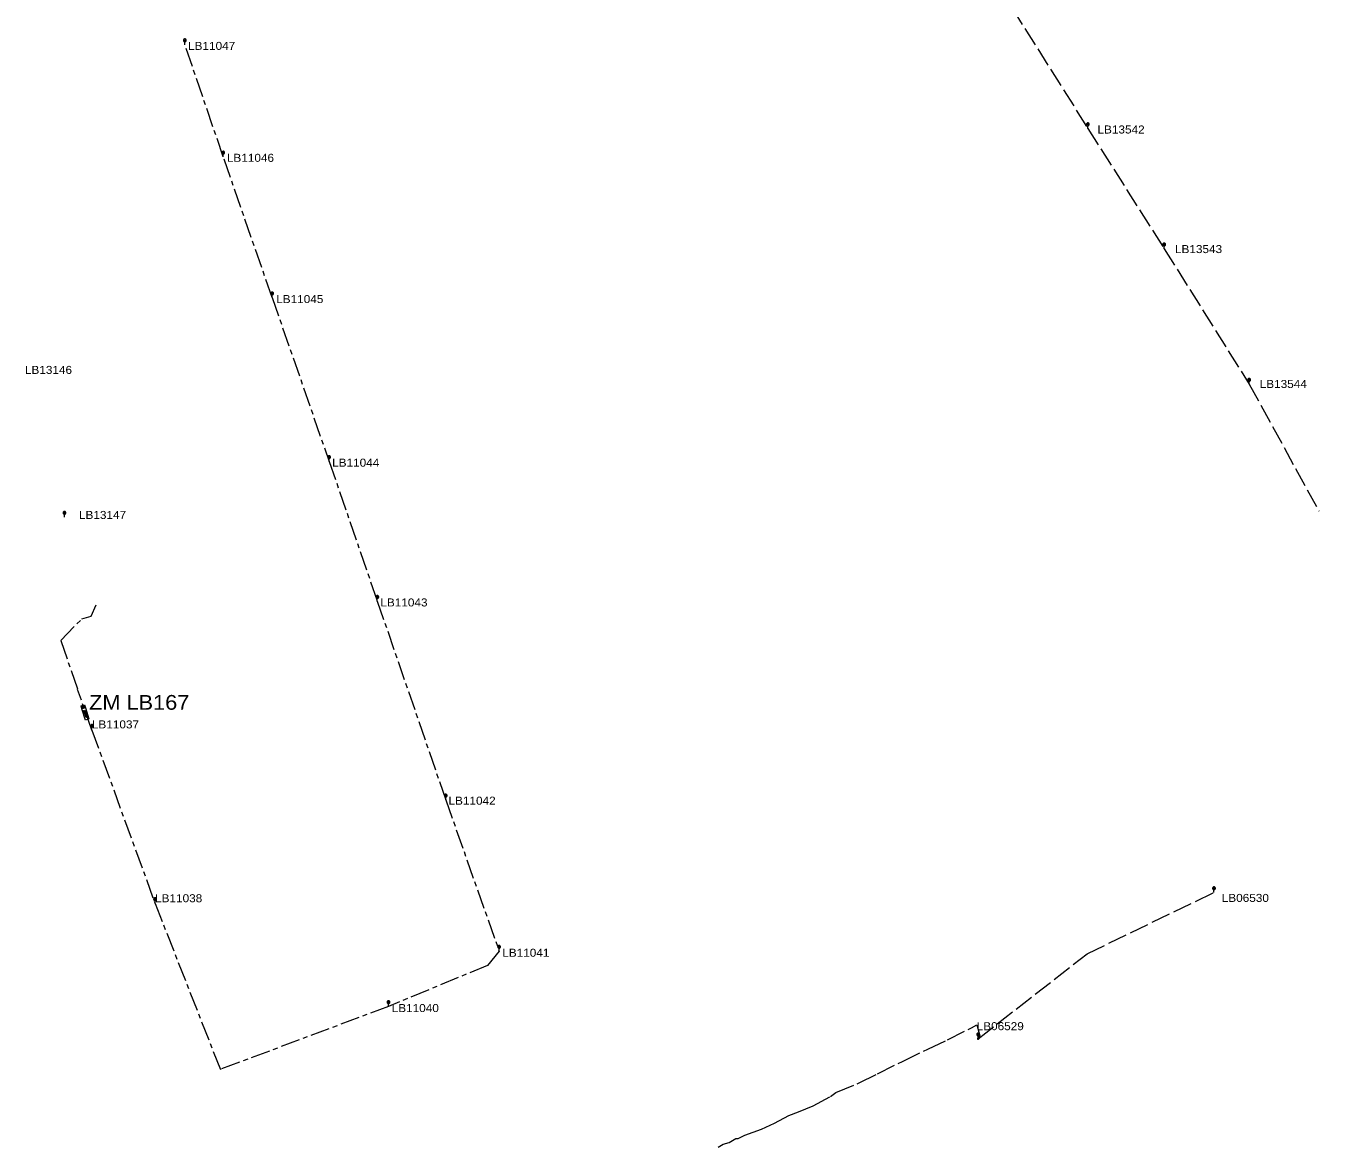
# Model space of a CAD drawing. Extents: x -691843 to -691118, y -976392 to -975793.
# Drawn here: x -691478 to -691127.9, y -976386.7 to -976083.1 of the extents above; entities that cross this region are included whole.
import ezdxf

# ---------------------------------------------------------------- set-up
doc = ezdxf.new("R2010")
doc.units = 0
doc.header["$LTSCALE"] = 0.87
doc.linetypes.add('LONG_DASH_SHORT_DASH', pattern=[9.9, 6, -1.2, 1.5, -1.2])
doc.linetypes.add('LONG_DASHED', pattern=[7.5, 6, -1.5])
doc.layers.add('1', color=7, linetype='Continuous', lineweight=13)

msp = doc.modelspace()

# ---------------------------------------------------------------- hatches: boundary and pattern name
at = {"layer": '1'}
for points in [[(-691462.091, -976266.926), (-691461.855, -976267.69), (-691462.81, -976267.986), (-691463.046, -976267.222)], [(-691462.742, -976267.36), (-691462.264, -976267.212), (-691462.15, -976267.58), (-691462.229, -976267.605), (-691462.31, -976267.345), (-691462.415, -976267.378), (-691462.345, -976267.603), (-691462.424, -976267.628), (-691462.494, -976267.402), (-691462.621, -976267.442), (-691462.541, -976267.701), (-691462.628, -976267.728)], [(-691462.059, -976268.381), (-691461.467, -976270.292), (-691461.658, -976270.351), (-691462.25, -976268.441)]]:
    msp.add_hatch(color=256, dxfattribs=at).paths.add_polyline_path(points)

# ---------------------------------------------------------------- linework, layer by layer
for p, q in [((-691435.212, -976086.724), (-691434.682, -976087.254)), ((-691435.212, -976087.254), (-691434.682, -976086.724)), ((-691434.947, -976088.139), (-691434.947, -976087.364)), ((-691190.775, -976109.465), (-691190.245, -976109.995)), ((-691190.775, -976109.995), (-691190.245, -976109.465)), ((-691190.51, -976110.88), (-691190.51, -976110.105)), ((-691424.811, -976117.136), (-691424.281, -976117.666)), ((-691424.811, -976117.666), (-691424.281, -976117.136)), ((-691424.546, -976118.551), (-691424.546, -976117.776)), ((-691170.125, -976142.015), (-691169.595, -976142.545)), ((-691170.125, -976142.545), (-691169.595, -976142.015)), ((-691169.86, -976143.43), (-691169.86, -976142.655)), ((-691411.569, -976155.247), (-691411.039, -976155.777)), ((-691411.569, -976155.777), (-691411.039, -976155.247)), ((-691411.304, -976156.662), (-691411.304, -976155.887)), ((-691147.115, -976178.655), (-691146.585, -976179.185)), ((-691147.115, -976179.185), (-691146.585, -976178.655)), ((-691146.85, -976180.07), (-691146.85, -976179.295)), ((-691396.157, -976199.577), (-691395.627, -976200.107)), ((-691396.157, -976200.107), (-691395.627, -976199.577)), ((-691395.892, -976200.992), (-691395.892, -976200.217)), ((-691467.801, -976214.654), (-691467.271, -976215.184)), ((-691467.801, -976215.184), (-691467.271, -976214.654)), ((-691467.536, -976216.069), (-691467.536, -976215.294)), ((-691383.111, -976237.436), (-691382.581, -976237.966)), ((-691383.111, -976237.966), (-691382.581, -976237.436)), ((-691382.846, -976238.851), (-691382.846, -976238.076)), ((-691460.372, -976272.356), (-691459.842, -976272.886)), ((-691460.372, -976272.886), (-691459.842, -976272.356)), ((-691460.107, -976273.771), (-691460.107, -976272.996)), ((-691364.591, -976291.215), (-691364.061, -976291.745)), ((-691364.591, -976291.745), (-691364.061, -976291.215)), ((-691364.326, -976292.63), (-691364.326, -976291.855)), ((-691156.645, -976316.315), (-691156.115, -976316.845)), ((-691156.645, -976316.845), (-691156.115, -976316.315)), ((-691443.282, -976319.263), (-691442.752, -976319.793)), ((-691443.282, -976319.793), (-691442.752, -976319.263)), ((-691443.017, -976320.678), (-691443.017, -976319.903)), ((-691156.38, -976317.73), (-691156.38, -976316.955)), ((-691350.155, -976332.168), (-691349.625, -976332.698)), ((-691350.155, -976332.698), (-691349.625, -976332.168)), ((-691349.89, -976333.583), (-691349.89, -976332.808)), ((-691380.08, -976347.145), (-691379.55, -976347.675)), ((-691380.08, -976347.675), (-691379.55, -976347.145)), ((-691379.815, -976348.56), (-691379.815, -976347.785)), ((-691220.475, -976355.885), (-691219.945, -976356.415)), ((-691220.475, -976356.415), (-691219.945, -976355.885)), ((-691220.21, -976357.3), (-691220.21, -976356.525))]:
    msp.add_line(p, q, dxfattribs=at)
at = {"layer": '1', "linetype": 'LONG_DASHED'}
for p, q in [((-691190.51, -976110.88), (-691169.86, -976143.43)), ((-691169.86, -976143.43), (-691146.85, -976180.07)), ((-691146.85, -976180.07), (-691127.92, -976214.52))]:
    msp.add_line(p, q, dxfattribs=at)
at = {"layer": '1', "linetype": 'LONG_DASH_SHORT_DASH'}
for p, q in [((-691411.304, -976156.662), (-691395.892, -976200.992)), ((-691462.797, -976243.605), (-691460.288, -976242.863)), ((-691460.288, -976242.863), (-691458.924, -976239.813)), ((-691468.513, -976249.481), (-691462.797, -976243.605)), ((-691468.513, -976249.481), (-691463.975, -976262.752)), ((-691460.107, -976273.771), (-691463.975, -976262.752)), ((-691364.326, -976292.63), (-691349.89, -976333.583)), ((-691379.815, -976348.56), (-691425.332, -976365.623))]:
    msp.add_line(p, q, dxfattribs=at)
at = {"layer": '1', "linetype": 'LONG_DASHED'}
for points in [[(-691234.33, -976047.73), (-691211.05, -976078.27), (-691190.51, -976110.88)], [(-691220.21, -976357.3), (-691190.733, -976334.3), (-691156.38, -976317.73)]]:
    msp.add_lwpolyline(points, dxfattribs=at)
at = {"layer": '1'}
for points in [[(-691434.572, -976086.989), (-691434.578, -976086.924), (-691434.595, -976086.861), (-691434.622, -976086.802), (-691434.66, -976086.748), (-691434.706, -976086.702), (-691434.76, -976086.664), (-691434.819, -976086.637), (-691434.882, -976086.62), (-691434.947, -976086.614), (-691435.012, -976086.62), (-691435.075, -976086.637), (-691435.134, -976086.664), (-691435.188, -976086.702), (-691435.234, -976086.748), (-691435.272, -976086.802), (-691435.299, -976086.861), (-691435.316, -976086.924), (-691435.322, -976086.989), (-691435.316, -976087.054), (-691435.299, -976087.117), (-691435.272, -976087.176), (-691435.234, -976087.23), (-691435.188, -976087.276), (-691435.134, -976087.314), (-691435.075, -976087.341), (-691435.012, -976087.358), (-691434.947, -976087.364), (-691434.882, -976087.358), (-691434.819, -976087.341), (-691434.76, -976087.314), (-691434.706, -976087.276), (-691434.66, -976087.23), (-691434.622, -976087.176), (-691434.595, -976087.117), (-691434.578, -976087.054)], [(-691190.135, -976109.73), (-691190.141, -976109.665), (-691190.158, -976109.602), (-691190.185, -976109.543), (-691190.223, -976109.489), (-691190.269, -976109.443), (-691190.322, -976109.405), (-691190.382, -976109.378), (-691190.445, -976109.361), (-691190.51, -976109.355), (-691190.575, -976109.361), (-691190.638, -976109.378), (-691190.698, -976109.405), (-691190.751, -976109.443), (-691190.797, -976109.489), (-691190.835, -976109.543), (-691190.862, -976109.602), (-691190.879, -976109.665), (-691190.885, -976109.73), (-691190.879, -976109.795), (-691190.862, -976109.858), (-691190.835, -976109.918), (-691190.797, -976109.971), (-691190.751, -976110.017), (-691190.698, -976110.055), (-691190.638, -976110.082), (-691190.575, -976110.099), (-691190.51, -976110.105), (-691190.445, -976110.099), (-691190.382, -976110.082), (-691190.322, -976110.055), (-691190.269, -976110.017), (-691190.223, -976109.971), (-691190.185, -976109.918), (-691190.158, -976109.858), (-691190.141, -976109.795)], [(-691424.171, -976117.401), (-691424.177, -976117.336), (-691424.194, -976117.273), (-691424.221, -976117.214), (-691424.259, -976117.16), (-691424.305, -976117.114), (-691424.358, -976117.076), (-691424.418, -976117.049), (-691424.481, -976117.032), (-691424.546, -976117.026), (-691424.611, -976117.032), (-691424.674, -976117.049), (-691424.734, -976117.076), (-691424.787, -976117.114), (-691424.833, -976117.16), (-691424.871, -976117.214), (-691424.898, -976117.273), (-691424.915, -976117.336), (-691424.921, -976117.401), (-691424.915, -976117.466), (-691424.898, -976117.529), (-691424.871, -976117.589), (-691424.833, -976117.642), (-691424.787, -976117.688), (-691424.734, -976117.726), (-691424.674, -976117.753), (-691424.611, -976117.77), (-691424.546, -976117.776), (-691424.481, -976117.77), (-691424.418, -976117.753), (-691424.358, -976117.726), (-691424.305, -976117.688), (-691424.259, -976117.642), (-691424.221, -976117.589), (-691424.194, -976117.529), (-691424.177, -976117.466)], [(-691169.485, -976142.28), (-691169.491, -976142.215), (-691169.508, -976142.152), (-691169.535, -976142.092), (-691169.573, -976142.039), (-691169.619, -976141.993), (-691169.672, -976141.955), (-691169.732, -976141.928), (-691169.795, -976141.911), (-691169.86, -976141.905), (-691169.925, -976141.911), (-691169.988, -976141.928), (-691170.048, -976141.955), (-691170.101, -976141.993), (-691170.147, -976142.039), (-691170.185, -976142.092), (-691170.212, -976142.152), (-691170.229, -976142.215), (-691170.235, -976142.28), (-691170.229, -976142.345), (-691170.212, -976142.408), (-691170.185, -976142.468), (-691170.147, -976142.521), (-691170.101, -976142.567), (-691170.048, -976142.605), (-691169.988, -976142.632), (-691169.925, -976142.649), (-691169.86, -976142.655), (-691169.795, -976142.649), (-691169.732, -976142.632), (-691169.672, -976142.605), (-691169.619, -976142.567), (-691169.573, -976142.521), (-691169.535, -976142.468), (-691169.508, -976142.408), (-691169.491, -976142.345)], [(-691410.929, -976155.512), (-691410.935, -976155.447), (-691410.952, -976155.384), (-691410.979, -976155.325), (-691411.017, -976155.271), (-691411.063, -976155.225), (-691411.116, -976155.187), (-691411.176, -976155.16), (-691411.239, -976155.143), (-691411.304, -976155.137), (-691411.369, -976155.143), (-691411.432, -976155.16), (-691411.492, -976155.187), (-691411.545, -976155.225), (-691411.591, -976155.271), (-691411.629, -976155.325), (-691411.656, -976155.384), (-691411.673, -976155.447), (-691411.679, -976155.512), (-691411.673, -976155.577), (-691411.656, -976155.64), (-691411.629, -976155.7), (-691411.591, -976155.753), (-691411.545, -976155.799), (-691411.492, -976155.837), (-691411.432, -976155.864), (-691411.369, -976155.881), (-691411.304, -976155.887), (-691411.239, -976155.881), (-691411.176, -976155.864), (-691411.116, -976155.837), (-691411.063, -976155.799), (-691411.017, -976155.753), (-691410.979, -976155.7), (-691410.952, -976155.64), (-691410.935, -976155.577)], [(-691146.475, -976178.92), (-691146.481, -976178.855), (-691146.498, -976178.792), (-691146.525, -976178.732), (-691146.563, -976178.679), (-691146.609, -976178.633), (-691146.662, -976178.595), (-691146.722, -976178.568), (-691146.785, -976178.551), (-691146.85, -976178.545), (-691146.915, -976178.551), (-691146.978, -976178.568), (-691147.038, -976178.595), (-691147.091, -976178.633), (-691147.137, -976178.679), (-691147.175, -976178.732), (-691147.202, -976178.792), (-691147.219, -976178.855), (-691147.225, -976178.92), (-691147.219, -976178.985), (-691147.202, -976179.048), (-691147.175, -976179.107), (-691147.137, -976179.161), (-691147.091, -976179.207), (-691147.038, -976179.245), (-691146.978, -976179.272), (-691146.915, -976179.289), (-691146.85, -976179.295), (-691146.785, -976179.289), (-691146.722, -976179.272), (-691146.662, -976179.245), (-691146.609, -976179.207), (-691146.563, -976179.161), (-691146.525, -976179.107), (-691146.498, -976179.048), (-691146.481, -976178.985)], [(-691395.517, -976199.842), (-691395.523, -976199.777), (-691395.54, -976199.714), (-691395.567, -976199.655), (-691395.605, -976199.601), (-691395.651, -976199.555), (-691395.704, -976199.517), (-691395.764, -976199.49), (-691395.827, -976199.473), (-691395.892, -976199.467), (-691395.957, -976199.473), (-691396.02, -976199.49), (-691396.08, -976199.517), (-691396.133, -976199.555), (-691396.179, -976199.601), (-691396.217, -976199.655), (-691396.244, -976199.714), (-691396.261, -976199.777), (-691396.267, -976199.842), (-691396.261, -976199.907), (-691396.244, -976199.97), (-691396.217, -976200.03), (-691396.179, -976200.083), (-691396.133, -976200.129), (-691396.08, -976200.167), (-691396.02, -976200.194), (-691395.957, -976200.211), (-691395.892, -976200.217), (-691395.827, -976200.211), (-691395.764, -976200.194), (-691395.704, -976200.167), (-691395.651, -976200.129), (-691395.605, -976200.083), (-691395.567, -976200.03), (-691395.54, -976199.97), (-691395.523, -976199.907)], [(-691467.161, -976214.919), (-691467.167, -976214.854), (-691467.184, -976214.791), (-691467.211, -976214.732), (-691467.249, -976214.678), (-691467.295, -976214.632), (-691467.348, -976214.594), (-691467.408, -976214.567), (-691467.471, -976214.55), (-691467.536, -976214.544), (-691467.601, -976214.55), (-691467.664, -976214.567), (-691467.724, -976214.594), (-691467.777, -976214.632), (-691467.823, -976214.678), (-691467.861, -976214.732), (-691467.888, -976214.791), (-691467.905, -976214.854), (-691467.911, -976214.919), (-691467.905, -976214.984), (-691467.888, -976215.047), (-691467.861, -976215.107), (-691467.823, -976215.16), (-691467.777, -976215.206), (-691467.724, -976215.244), (-691467.664, -976215.271), (-691467.601, -976215.288), (-691467.536, -976215.294), (-691467.471, -976215.288), (-691467.408, -976215.271), (-691467.348, -976215.244), (-691467.295, -976215.206), (-691467.249, -976215.16), (-691467.211, -976215.107), (-691467.184, -976215.047), (-691467.167, -976214.984)], [(-691382.471, -976237.701), (-691382.477, -976237.636), (-691382.494, -976237.573), (-691382.521, -976237.514), (-691382.559, -976237.46), (-691382.605, -976237.414), (-691382.658, -976237.376), (-691382.718, -976237.349), (-691382.781, -976237.332), (-691382.846, -976237.326), (-691382.911, -976237.332), (-691382.974, -976237.349), (-691383.034, -976237.376), (-691383.087, -976237.414), (-691383.133, -976237.46), (-691383.171, -976237.514), (-691383.198, -976237.573), (-691383.215, -976237.636), (-691383.221, -976237.701), (-691383.215, -976237.766), (-691383.198, -976237.829), (-691383.171, -976237.888), (-691383.133, -976237.942), (-691383.087, -976237.988), (-691383.034, -976238.026), (-691382.974, -976238.053), (-691382.911, -976238.07), (-691382.846, -976238.076), (-691382.781, -976238.07), (-691382.718, -976238.053), (-691382.658, -976238.026), (-691382.605, -976237.988), (-691382.559, -976237.942), (-691382.521, -976237.888), (-691382.494, -976237.829), (-691382.477, -976237.766)], [(-691462.091, -976266.926), (-691461.855, -976267.69), (-691462.81, -976267.986), (-691463.046, -976267.222)], [(-691462.091, -976266.926), (-691461.855, -976267.69), (-691462.81, -976267.986), (-691463.046, -976267.222)], [(-691462.742, -976267.36), (-691462.264, -976267.212), (-691462.15, -976267.58), (-691462.229, -976267.605), (-691462.31, -976267.345), (-691462.415, -976267.378), (-691462.345, -976267.603), (-691462.424, -976267.628), (-691462.494, -976267.402), (-691462.621, -976267.442), (-691462.541, -976267.701), (-691462.628, -976267.728)], [(-691462.059, -976268.381), (-691461.467, -976270.292), (-691461.658, -976270.351), (-691462.25, -976268.441)], [(-691459.732, -976272.621), (-691459.738, -976272.556), (-691459.755, -976272.493), (-691459.782, -976272.433), (-691459.82, -976272.38), (-691459.866, -976272.334), (-691459.92, -976272.296), (-691459.979, -976272.269), (-691460.042, -976272.252), (-691460.107, -976272.246), (-691460.172, -976272.252), (-691460.235, -976272.269), (-691460.294, -976272.296), (-691460.348, -976272.334), (-691460.394, -976272.38), (-691460.432, -976272.433), (-691460.459, -976272.493), (-691460.476, -976272.556), (-691460.482, -976272.621), (-691460.476, -976272.686), (-691460.459, -976272.749), (-691460.432, -976272.808), (-691460.394, -976272.862), (-691460.348, -976272.908), (-691460.294, -976272.946), (-691460.235, -976272.973), (-691460.172, -976272.99), (-691460.107, -976272.996), (-691460.042, -976272.99), (-691459.979, -976272.973), (-691459.92, -976272.946), (-691459.866, -976272.908), (-691459.82, -976272.862), (-691459.782, -976272.808), (-691459.755, -976272.749), (-691459.738, -976272.686)], [(-691363.951, -976291.48), (-691363.957, -976291.415), (-691363.974, -976291.352), (-691364.001, -976291.293), (-691364.039, -976291.239), (-691364.085, -976291.193), (-691364.138, -976291.155), (-691364.198, -976291.128), (-691364.261, -976291.111), (-691364.326, -976291.105), (-691364.391, -976291.111), (-691364.454, -976291.128), (-691364.514, -976291.155), (-691364.567, -976291.193), (-691364.613, -976291.239), (-691364.651, -976291.293), (-691364.678, -976291.352), (-691364.695, -976291.415), (-691364.701, -976291.48), (-691364.695, -976291.545), (-691364.678, -976291.608), (-691364.651, -976291.668), (-691364.613, -976291.721), (-691364.567, -976291.767), (-691364.514, -976291.805), (-691364.454, -976291.832), (-691364.391, -976291.849), (-691364.326, -976291.855), (-691364.261, -976291.849), (-691364.198, -976291.832), (-691364.138, -976291.805), (-691364.085, -976291.767), (-691364.039, -976291.721), (-691364.001, -976291.668), (-691363.974, -976291.608), (-691363.957, -976291.545)], [(-691156.005, -976316.58), (-691156.011, -976316.515), (-691156.028, -976316.452), (-691156.055, -976316.393), (-691156.093, -976316.339), (-691156.139, -976316.293), (-691156.192, -976316.255), (-691156.252, -976316.228), (-691156.315, -976316.211), (-691156.38, -976316.205), (-691156.445, -976316.211), (-691156.508, -976316.228), (-691156.568, -976316.255), (-691156.621, -976316.293), (-691156.667, -976316.339), (-691156.705, -976316.393), (-691156.732, -976316.452), (-691156.749, -976316.515), (-691156.755, -976316.58), (-691156.749, -976316.645), (-691156.732, -976316.708), (-691156.705, -976316.768), (-691156.667, -976316.821), (-691156.621, -976316.867), (-691156.568, -976316.905), (-691156.508, -976316.932), (-691156.445, -976316.949), (-691156.38, -976316.955), (-691156.315, -976316.949), (-691156.252, -976316.932), (-691156.192, -976316.905), (-691156.139, -976316.867), (-691156.093, -976316.821), (-691156.055, -976316.768), (-691156.028, -976316.708), (-691156.011, -976316.645)], [(-691442.642, -976319.528), (-691442.648, -976319.463), (-691442.665, -976319.4), (-691442.692, -976319.34), (-691442.73, -976319.287), (-691442.776, -976319.241), (-691442.83, -976319.203), (-691442.889, -976319.176), (-691442.952, -976319.159), (-691443.017, -976319.153), (-691443.082, -976319.159), (-691443.145, -976319.176), (-691443.204, -976319.203), (-691443.258, -976319.241), (-691443.304, -976319.287), (-691443.342, -976319.34), (-691443.369, -976319.4), (-691443.386, -976319.463), (-691443.392, -976319.528), (-691443.386, -976319.593), (-691443.369, -976319.656), (-691443.342, -976319.715), (-691443.304, -976319.769), (-691443.258, -976319.815), (-691443.204, -976319.853), (-691443.145, -976319.88), (-691443.082, -976319.897), (-691443.017, -976319.903), (-691442.952, -976319.897), (-691442.889, -976319.88), (-691442.83, -976319.853), (-691442.776, -976319.815), (-691442.73, -976319.769), (-691442.692, -976319.715), (-691442.665, -976319.656), (-691442.648, -976319.593)], [(-691349.515, -976332.433), (-691349.521, -976332.368), (-691349.538, -976332.305), (-691349.565, -976332.246), (-691349.603, -976332.192), (-691349.649, -976332.146), (-691349.702, -976332.108), (-691349.762, -976332.081), (-691349.825, -976332.064), (-691349.89, -976332.058), (-691349.955, -976332.064), (-691350.018, -976332.081), (-691350.078, -976332.108), (-691350.131, -976332.146), (-691350.177, -976332.192), (-691350.215, -976332.246), (-691350.242, -976332.305), (-691350.259, -976332.368), (-691350.265, -976332.433), (-691350.259, -976332.498), (-691350.242, -976332.561), (-691350.215, -976332.621), (-691350.177, -976332.674), (-691350.131, -976332.72), (-691350.078, -976332.758), (-691350.018, -976332.785), (-691349.955, -976332.802), (-691349.89, -976332.808), (-691349.825, -976332.802), (-691349.762, -976332.785), (-691349.702, -976332.758), (-691349.649, -976332.72), (-691349.603, -976332.674), (-691349.565, -976332.621), (-691349.538, -976332.561), (-691349.521, -976332.498)], [(-691379.44, -976347.41), (-691379.446, -976347.345), (-691379.463, -976347.282), (-691379.49, -976347.222), (-691379.528, -976347.169), (-691379.574, -976347.123), (-691379.628, -976347.085), (-691379.687, -976347.058), (-691379.75, -976347.041), (-691379.815, -976347.035), (-691379.88, -976347.041), (-691379.943, -976347.058), (-691380.003, -976347.085), (-691380.056, -976347.123), (-691380.102, -976347.169), (-691380.14, -976347.222), (-691380.167, -976347.282), (-691380.184, -976347.345), (-691380.19, -976347.41), (-691380.184, -976347.475), (-691380.167, -976347.538), (-691380.14, -976347.598), (-691380.102, -976347.651), (-691380.056, -976347.697), (-691380.003, -976347.735), (-691379.943, -976347.762), (-691379.88, -976347.779), (-691379.815, -976347.785), (-691379.75, -976347.779), (-691379.687, -976347.762), (-691379.628, -976347.735), (-691379.574, -976347.697), (-691379.528, -976347.651), (-691379.49, -976347.598), (-691379.463, -976347.538), (-691379.446, -976347.475)], [(-691219.835, -976356.15), (-691219.841, -976356.085), (-691219.858, -976356.022), (-691219.885, -976355.962), (-691219.923, -976355.909), (-691219.969, -976355.863), (-691220.022, -976355.825), (-691220.082, -976355.798), (-691220.145, -976355.781), (-691220.21, -976355.775), (-691220.275, -976355.781), (-691220.338, -976355.798), (-691220.398, -976355.825), (-691220.451, -976355.863), (-691220.497, -976355.909), (-691220.535, -976355.962), (-691220.562, -976356.022), (-691220.579, -976356.085), (-691220.585, -976356.15), (-691220.579, -976356.215), (-691220.562, -976356.278), (-691220.535, -976356.338), (-691220.497, -976356.391), (-691220.451, -976356.437), (-691220.398, -976356.475), (-691220.338, -976356.502), (-691220.275, -976356.519), (-691220.21, -976356.525), (-691220.145, -976356.519), (-691220.082, -976356.502), (-691220.022, -976356.475), (-691219.969, -976356.437), (-691219.923, -976356.391), (-691219.885, -976356.338), (-691219.858, -976356.278), (-691219.841, -976356.215)], [(-691220.02, -976357.3), (-691220.023, -976357.267), (-691220.031, -976357.235), (-691220.045, -976357.205), (-691220.064, -976357.178), (-691220.088, -976357.154), (-691220.115, -976357.135), (-691220.145, -976357.121), (-691220.177, -976357.113), (-691220.21, -976357.11), (-691220.243, -976357.113), (-691220.275, -976357.121), (-691220.305, -976357.135), (-691220.332, -976357.154), (-691220.356, -976357.178), (-691220.375, -976357.205), (-691220.389, -976357.235), (-691220.397, -976357.267), (-691220.4, -976357.3), (-691220.397, -976357.333), (-691220.389, -976357.365), (-691220.375, -976357.395), (-691220.356, -976357.422), (-691220.332, -976357.446), (-691220.305, -976357.465), (-691220.275, -976357.479), (-691220.243, -976357.487), (-691220.21, -976357.49), (-691220.177, -976357.487), (-691220.145, -976357.479), (-691220.115, -976357.465), (-691220.088, -976357.446), (-691220.064, -976357.422), (-691220.045, -976357.395), (-691220.031, -976357.365), (-691220.023, -976357.333)], [(-691220.16, -976357.3), (-691220.161, -976357.291), (-691220.163, -976357.283), (-691220.167, -976357.275), (-691220.172, -976357.268), (-691220.178, -976357.262), (-691220.185, -976357.257), (-691220.193, -976357.253), (-691220.201, -976357.251), (-691220.21, -976357.25), (-691220.219, -976357.251), (-691220.227, -976357.253), (-691220.235, -976357.257), (-691220.242, -976357.262), (-691220.248, -976357.268), (-691220.253, -976357.275), (-691220.257, -976357.283), (-691220.259, -976357.291), (-691220.26, -976357.3), (-691220.259, -976357.309), (-691220.257, -976357.317), (-691220.253, -976357.325), (-691220.248, -976357.332), (-691220.242, -976357.338), (-691220.235, -976357.343), (-691220.227, -976357.347), (-691220.219, -976357.349), (-691220.21, -976357.35), (-691220.201, -976357.349), (-691220.193, -976357.347), (-691220.185, -976357.343), (-691220.178, -976357.338), (-691220.172, -976357.332), (-691220.167, -976357.325), (-691220.163, -976357.317), (-691220.161, -976357.309)]]:
    msp.add_lwpolyline(points, close=True, dxfattribs=at)
at = {"layer": '1', "linetype": 'LONG_DASH_SHORT_DASH'}
for points in [[(-691411.304, -976156.662), (-691424.546, -976118.551), (-691434.947, -976088.139)], [(-691395.892, -976200.992), (-691382.846, -976238.851), (-691364.326, -976292.63)], [(-691460.107, -976273.771), (-691443.017, -976320.678), (-691425.332, -976365.623)], [(-691349.89, -976333.583), (-691352.999, -976337.451), (-691379.815, -976348.56)], [(-691290.57, -976386.67), (-691289.25, -976385.84), (-691287.61, -976385.43), (-691285.8, -976384.37), (-691285.16, -976384.33), (-691283.36, -976383.46), (-691278.85, -976381.78), (-691275.36, -976380.17), (-691271.43, -976378.13), (-691268.88, -976377.08), (-691264.91, -976375.53), (-691260.17, -976372.92), (-691258.72, -976371.91), (-691252.46, -976369.28), (-691247.5, -976366.82), (-691240.66, -976363.44), (-691233.81, -976360.13), (-691228.55, -976357.63), (-691222.02, -976354.38), (-691220.56, -976353.56), (-691219.79, -976356.54), (-691220.21, -976357.3)]]:
    msp.add_lwpolyline(points, dxfattribs=at)
at = {"layer": '1'}
msp.add_lwpolyline([(-691461.855, -976267.69), (-691460.907, -976270.746), (-691461.863, -976271.042), (-691462.81, -976267.986)], dxfattribs=at)

# ---------------------------------------------------------------- texts
at = {"layer": '1', "width": 1.1}
for s, height, p in [('LB11047', 2.167, (-691434.072, -976089.581)), ('LB13542', 2.167, (-691187.911, -976112.22)), ('LB11046', 2.167, (-691423.567, -976119.888)), ('LB13543', 2.167, (-691166.944, -976144.599)), ('LB11045', 2.167, (-691410.216, -976158.13)), ('LB13146', 2.167, (-691478.24, -976177.312)), ('LB13544', 2.167, (-691144.005, -976181.117)), ('LB11044', 2.167, (-691395.073, -976202.428)), ('LB13147', 2.167, (-691463.606, -976216.582)), ('LB11043', 2.167, (-691382.023, -976240.274)), ('ZM LB167', 4, (-691460.873, -976268.25)), ('LB11037', 2.167, (-691460.11, -976273.296)), ('LB11042', 2.167, (-691363.58, -976293.944)), ('LB11038', 2.167, (-691443, -976320.363)), ('LB06530', 2.167, (-691154.276, -976320.275)), ('LB11041', 2.167, (-691349.028, -976335.122)), ('LB11040', 2.167, (-691378.956, -976350.096)), ('LB06529', 2.167, (-691220.619, -976355.002))]:
    msp.add_text(s, height=height, dxfattribs=at).set_placement(p)

doc.saveas('drawing.dxf')
